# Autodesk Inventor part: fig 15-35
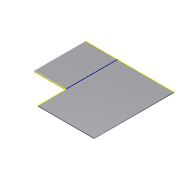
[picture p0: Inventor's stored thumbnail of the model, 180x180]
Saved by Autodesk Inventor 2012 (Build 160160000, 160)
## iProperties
Created: 2005-03
Part Number: fig 15-35
Document SubType Name: Sheet Metal
Designer: CADCIM
Manufacturer: Standard
Standards Organization: Custom
Density: 1 g/cm^3
Sheet Metal Rule: Default
Material: Default
Author: CADCIM
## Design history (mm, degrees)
node "Face1"
  sketch "Sketch1"
    geometry: L1 (31.393, 35.714)-(-19.875, 35.714); L2 (-19.875, 35.714)-(-19.875, 5.625); L3 (-19.875, 5.625)-(-1.5, 5.625); L4 (-1.5, 5.625)-(-1.5, -10.705); L5 (-1.5, -10.705)-(31.393, -10.705); L6 (31.393, -10.705)-(31.393, 35.714)
    constraints: 12 end point, 4 parallel, 1 horizontal, 1 perpendicular
sketch "Sketch3"
  geometry: L1 (18.375, -30.089)-(18.375, 0); L2 (18.375, -46.42)-(18.375, -30.089) reference; L3 (18.375, -30.089)-(0, -30.089) reference; L4 (0, 0)-(51.268, 0) reference
  constraints: 3 point on line, 2 end point, 1 vertical
body "Solid1"
face "Plate1" dims "Thickness" = 0.5
other parameters: "BendRadius" = 0.5 (= Thickness), "BendReliefWidth" = 0.5 (= Thickness), "BendReliefDepth" = 0.25 (= 0.5 x Thickness), "CornerReliefSize" = 2 (= 4 x Thickness), "SeamGap" = 0.01, "MinimumRemnant" = 1 (= 2 x Thickness), "TransitionRadius" = 0.5 (= BendRadius), "d0" = 0.5 (= BendRadius), "JacobiRadiusSize" = 0.5 (= Thickness), "GapSize" = 0.5 (= Thickness)
